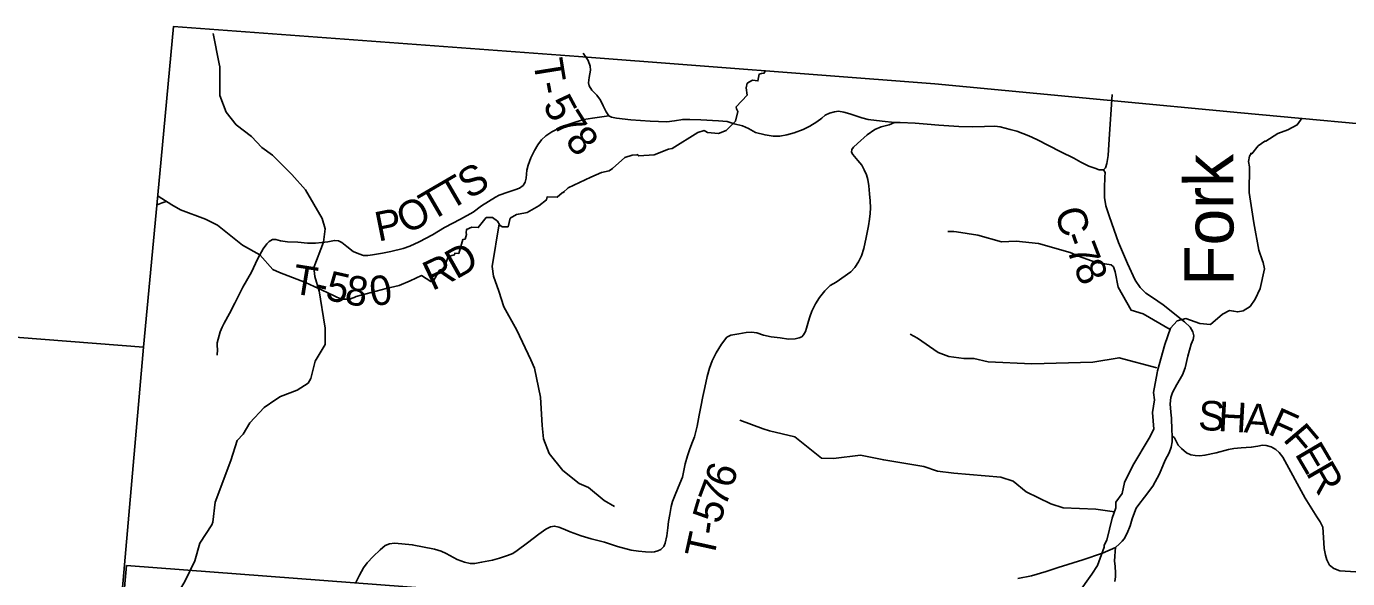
# Model space of a CAD drawing. Extents: x 1878108 to 2183446, y 146837 to 508383.
# Drawn here: x 1945764 to 1959185, y 305217 to 310824 of the extents above; entities that cross this region are included whole.
import ezdxf

# ---------------------------------------------------------------- set-up
doc = ezdxf.new("R2010")
doc.units = 0
for name, color, linetype in [('GM_X_Adjacent_County', 7, 'Continuous'), ('GM_X_County', 7, 'Continuous'), ('GM_X_County_Road', 7, 'Continuous'), ('GM_X_County_Road_Text', 7, 'Continuous'), ('GM_X_Minor_River', 7, 'Continuous'), ('GM_X_Minor_River_Text', 7, 'Continuous'), ('GM_X_Section', 7, 'Continuous'), ('GM_X_Township', 7, 'Continuous'), ('GM_X_Township_Road', 7, 'Continuous'), ('GM_X_Township_Road_Text', 7, 'Continuous')]:
    doc.layers.add(name, color=color, linetype=linetype)

msp = doc.modelspace()

# ---------------------------------------------------------------- linework, layer by layer
at = {"layer": 'GM_X_Adjacent_County'}
for points in [[(1959932, 309778), (1958100, 309945), (1956742, 310075), (1954993, 310242), (1951372, 310518), (1947259, 310824), (1947119, 309329), (1946953, 307566), (1940781, 308049), (1940473, 308073), (1934622, 308532), (1932946, 308617), (1931071, 308772), (1925774, 309211), (1919831, 309702), (1917959, 309848)], [(1923046, 277654), (1923342, 280921), (1923726, 285166), (1924414, 292311), (1924469, 293153), (1924887, 299587), (1925256, 303586), (1925774, 309211), (1931071, 308772), (1932946, 308617), (1934622, 308532), (1940473, 308073), (1940781, 308049), (1946953, 307566), (1946499, 302372), (1946238, 299382), (1946067, 297426), (1944907, 283849), (1944903, 283729), (1945544, 283670), (1949278, 283311), (1954438, 282859), (1961539, 282259)]]:
    msp.add_lwpolyline(points, dxfattribs=at)
at = {"layer": 'GM_X_County'}
msp.add_lwpolyline([(1961539, 282259), (1954438, 282859), (1949278, 283311), (1945544, 283670), (1944903, 283729), (1944907, 283849), (1946067, 297426), (1946238, 299382), (1946499, 302372), (1946953, 307566), (1947119, 309329), (1947259, 310824), (1951372, 310518), (1954993, 310242), (1956742, 310075), (1958100, 309945), (1959932, 309778)], dxfattribs=at)
at = {"layer": 'GM_X_County_Road'}
for points in [[(1956794, 310133), (1956762, 309678), (1956752, 309514), (1956741, 309433), (1956727, 309389), (1956706, 309368), (1956723, 309340), (1956718, 309292), (1956715, 309185), (1956715, 309087), (1956728, 309001), (1956767, 308892), (1956857, 308631), (1956949, 308416), (1957026, 308247), (1957077, 308173), (1957134, 308114), (1957202, 308072), (1957313, 307996), (1957528, 307824), (1957586, 307769), (1957614, 307722), (1957622, 307681), (1957615, 307645), (1957597, 307596), (1957562, 307474), (1957536, 307357), (1957508, 307287), (1957452, 307188), (1957408, 307107), (1957390, 307056), (1957382, 306990), (1957391, 306907), (1957397, 306847), (1957398, 306727), (1957403, 306665), (1957427, 306645), (1957464, 306573), (1957499, 306539), (1957549, 306494), (1957592, 306474), (1957638, 306465), (1957684, 306464), (1957735, 306470), (1957849, 306493), (1957975, 306527), (1958030, 306538), (1958105, 306543), (1958207, 306550), (1958273, 306561), (1958321, 306570), (1958358, 306569), (1958409, 306555), (1958457, 306527), (1958490, 306496), (1958527, 306450), (1958753, 306033), (1958873, 305843), (1958908, 305792), (1958932, 305740), (1958938, 305687), (1958948, 305521), (1958960, 305453), (1958973, 305408), (1959001, 305354), (1959046, 305320), (1959106, 305297), (1959268, 305285)], [(1955837, 305216), (1955974, 305243), (1956122, 305288), (1956244, 305328), (1956496, 305408), (1956697, 305476), (1956829, 305534), (1956868, 305570), (1956894, 305595), (1956915, 305620), (1956947, 305677), (1956976, 305751), (1956997, 305823), (1957022, 305887), (1957038, 305931), (1957066, 305969), (1957122, 306042), (1957207, 306156), (1957273, 306280), (1957331, 306418), (1957371, 306495), (1957393, 306551), (1957402, 306606), (1957403, 306665)]]:
    msp.add_lwpolyline(points, dxfattribs=at)
at = {"layer": 'GM_X_Minor_River'}
for points in [[(1948737, 308134), (1948693, 308284), (1948683, 308375), (1948781, 308632), (1948798, 308767), (1948769, 308874), (1948598, 309163), (1948461, 309321), (1948265, 309518), (1948156, 309595), (1948051, 309705), (1947895, 309826), (1947793, 309954), (1947730, 310121), (1947728, 310413), (1947724, 310443), (1947663, 310751)], [(1947101, 309102), (1947243, 309012), (1947329, 308960), (1947582, 308866), (1947706, 308805), (1947840, 308697), (1947961, 308603), (1948135, 308503), (1948269, 308354), (1948334, 308324), (1948600, 308222), (1948818, 308123), (1948961, 308055), (1949047, 308055), (1949095, 308071), (1949113, 308083), (1949419, 308162), (1949551, 308192), (1949663, 308240), (1949779, 308293), (1949871, 308235), (1949899, 308239), (1949959, 308349), (1949991, 308359), (1950016, 308391), (1950050, 308487), (1950114, 308505), (1950116, 308521), (1950156, 308519), (1950196, 308659), (1950220, 308665), (1950234, 308711), (1950232, 308727), (1950236, 308763), (1950288, 308784), (1950354, 308782), (1950393, 308832), (1950435, 308882), (1950499, 308884), (1950548, 308848), (1950574, 308806), (1950598, 308788), (1950658, 308790), (1950678, 308876), (1950741, 308914), (1950763, 308919), (1950852, 308933), (1950971, 309001), (1951047, 309063), (1951053, 309093), (1951155, 309089), (1951205, 309133), (1951229, 309148), (1951217, 309137), (1951269, 309186), (1951497, 309292), (1951605, 309340), (1951683, 309356), (1951717, 309382), (1951843, 309493), (1951917, 309517), (1951967, 309521), (1951967, 309523), (1951985, 309509), (1952141, 309519), (1952287, 309576), (1952323, 309584), (1952586, 309748), (1952648, 309766), (1952684, 309748), (1952795, 309737), (1952874, 309767), (1952966, 309861), (1952992, 309961), (1952978, 309987), (1952974, 310007), (1953086, 310127), (1953075, 310201), (1953085, 310247), (1953139, 310279), (1953195, 310270), (1953207, 310338), (1953233, 310346), (1953260, 310351), (1953269, 310373)], [(1956446, 305061), (1956586, 305261), (1956643, 305351), (1956713, 305536), (1956713, 305556), (1956741, 305606), (1956792, 305830), (1956832, 305934), (1956830, 305992), (1956894, 306082), (1956919, 306192), (1957003, 306366), (1957168, 306643), (1957218, 306735), (1957202, 306903), (1957223, 307033), (1957215, 307105), (1957250, 307305), (1957254, 307327), (1957328, 307593), (1957387, 307759), (1957453, 307833), (1957541, 307857), (1957683, 307806), (1957791, 307798), (1957913, 307902), (1957985, 307938), (1958027, 307934), (1958069, 307924), (1958123, 307936), (1958195, 307981), (1958247, 308053), (1958297, 308163), (1958342, 308361), (1958326, 308427), (1958322, 308443), (1958282, 308551), (1958231, 308831), (1958184, 309139), (1958189, 309399), (1958177, 309453), (1958187, 309505), (1958205, 309535), (1958211, 309531), (1958199, 309535), (1958211, 309529), (1958275, 309611), (1958343, 309659), (1958353, 309659), (1958477, 309737), (1958577, 309774), (1958674, 309824), (1958707, 309871), (1958718, 309890)], [(1947093, 309012), (1947143, 309031), (1947185, 309047)], [(1950565, 308820), (1950494, 308387), (1950509, 308289), (1950563, 308135), (1950614, 307978), (1950747, 307740), (1950887, 307437), (1950925, 307352), (1950985, 307058), (1951002, 306773), (1951017, 306636), (1951073, 306487), (1951213, 306315), (1951379, 306181), (1951473, 306142), (1951634, 306008), (1951739, 305949)], [(1957383, 307746), (1957107, 307907), (1956987, 307941), (1956854, 308175), (1956825, 308332), (1956808, 308381), (1956782, 308403), (1956630, 308426), (1956450, 308490), (1956366, 308528), (1956045, 308620), (1955818, 308644), (1955671, 308638), (1955430, 308703), (1955213, 308737), (1955186, 308741), (1955125, 308741)], [(1948736, 308160), (1948800, 307760), (1948800, 307593), (1948698, 307425), (1948654, 307249), (1948627, 307202), (1948516, 307130), (1948345, 307067), (1948298, 307036), (1948180, 306953), (1948033, 306798), (1947965, 306684), (1947906, 306620), (1947842, 306417), (1947682, 305992), (1947659, 305788), (1947647, 305761), (1947526, 305578), (1947475, 305396), (1947374, 305186), (1947218, 304925), (1947066, 304787), (1947042, 304678), (1947028, 304297)], [(1957246, 307358), (1956864, 307459), (1956597, 307414), (1955979, 307396), (1955533, 307418), (1955389, 307452), (1955286, 307453), (1955133, 307472), (1955027, 307511), (1954816, 307658), (1954743, 307698)], [(1956818, 305896), (1956626, 305920), (1956297, 305936), (1956172, 305977), (1955919, 306099), (1955788, 306206), (1955662, 306247), (1955184, 306286), (1955019, 306307), (1954880, 306355), (1954473, 306421), (1954237, 306471), (1953964, 306437), (1953841, 306438), (1953569, 306655), (1953314, 306717), (1953247, 306739), (1953010, 306826)]]:
    msp.add_lwpolyline(points, dxfattribs=at)
at = {"layer": 'GM_X_Section'}
msp.add_lwpolyline([(1946780, 305351), (1953640, 304827), (1953129, 299324), (1946292, 299873), (1946481, 302005)], close=True, dxfattribs=at)
at = {"layer": 'GM_X_Township'}
msp.add_lwpolyline([(1961539, 282259), (1954438, 282859), (1949278, 283311), (1945544, 283670), (1944903, 283729), (1944907, 283849), (1946067, 297426), (1946238, 299382), (1946499, 302372), (1946953, 307566), (1947119, 309329), (1947259, 310824), (1951372, 310518), (1954993, 310242), (1956742, 310075), (1958100, 309945), (1959932, 309778)], dxfattribs=at)
at = {"layer": 'GM_X_Township_Road'}
for points in [[(1951421, 310554), (1951470, 310479), (1951491, 310421), (1951494, 310381), (1951482, 310304), (1951474, 310251), (1951481, 310220), (1951508, 310176), (1951559, 310125), (1951596, 310076), (1951624, 310019), (1951652, 309956), (1951681, 309915), (1951707, 309901), (1951757, 309894), (1951905, 309875), (1952102, 309862), (1952270, 309856), (1952346, 309864), (1952431, 309879), (1952505, 309880), (1952616, 309874), (1952796, 309867), (1952882, 309858), (1952954, 309834), (1953037, 309813), (1953098, 309787), (1953169, 309748), (1953268, 309722), (1953351, 309710), (1953418, 309710), (1953488, 309723), (1953563, 309745), (1953655, 309778), (1953722, 309810), (1953794, 309856), (1953844, 309891), (1953879, 309923), (1953921, 309943), (1953972, 309958), (1954015, 309962), (1954068, 309954), (1954130, 309937), (1954249, 309895), (1954314, 309879), (1954458, 309863), (1954581, 309850)], [(1947703, 307487), (1947704, 307544), (1947703, 307579), (1947703, 307611), (1947712, 307647), (1947734, 307723), (1947753, 307769), (1947773, 307811), (1947826, 307908), (1947881, 308013), (1947964, 308175), (1948051, 308329), (1948092, 308417), (1948120, 308475), (1948170, 308564), (1948206, 308616), (1948231, 308639), (1948264, 308660), (1948299, 308661), (1948345, 308648), (1948417, 308636), (1948523, 308632), (1948620, 308624), (1948702, 308624), (1948766, 308629), (1948825, 308636), (1948893, 308651), (1948933, 308646), (1948968, 308630), (1949019, 308590), (1949085, 308540), (1949140, 308513), (1949187, 308499), (1949231, 308499), (1949279, 308505), (1949382, 308523), (1949465, 308540), (1949591, 308569), (1949660, 308593), (1949754, 308636), (1949888, 308709), (1950011, 308782), (1950174, 308866), (1950303, 308938), (1950387, 309001), (1950531, 309089), (1950567, 309110), (1950654, 309142), (1950725, 309163), (1950773, 309181), (1950810, 309208), (1950831, 309243), (1950840, 309284), (1950848, 309363), (1950860, 309416), (1950888, 309489), (1950927, 309564), (1950959, 309620), (1950995, 309671), (1951041, 309712), (1951102, 309754), (1951169, 309788), (1951269, 309828), (1951350, 309855), (1951426, 309880), (1951515, 309894), (1951681, 309915)], [(1949111, 305178), (1949147, 305251), (1949190, 305326), (1949226, 305375), (1949286, 305441), (1949357, 305507), (1949410, 305551), (1949454, 305570), (1949502, 305575), (1949579, 305569), (1949683, 305560), (1949910, 305516), (1949978, 305494), (1950028, 305472), (1950139, 305411), (1950213, 305384), (1950272, 305371), (1950319, 305370), (1950388, 305382), (1950500, 305405), (1950570, 305424), (1950651, 305450), (1950704, 305473), (1950750, 305503), (1950856, 305580), (1950968, 305667), (1951041, 305718), (1951087, 305742), (1951128, 305750), (1951174, 305740), (1951218, 305723), (1951287, 305693), (1951401, 305652), (1951501, 305622), (1951636, 305585), (1951769, 305544), (1951908, 305506), (1951981, 305494), (1952052, 305488), (1952110, 305484), (1952145, 305488), (1952177, 305497), (1952209, 305513), (1952238, 305541), (1952254, 305577), (1952269, 305652), (1952279, 305733), (1952288, 305796), (1952299, 305869), (1952315, 305948), (1952329, 305998), (1952349, 306051), (1952384, 306142), (1952428, 306248), (1952456, 306382), (1952480, 306463), (1952503, 306534), (1952529, 306604), (1952551, 306657), (1952566, 306711), (1952578, 306766), (1952599, 306877), (1952614, 306960), (1952636, 307065), (1952656, 307157), (1952679, 307269), (1952703, 307353), (1952731, 307429), (1952772, 307510), (1952825, 307598), (1952879, 307667), (1952919, 307689), (1953001, 307702), (1953076, 307717), (1953130, 307718), (1953185, 307711), (1953253, 307689), (1953331, 307671), (1953421, 307660), (1953507, 307648), (1953574, 307652), (1953613, 307660), (1953640, 307672), (1953659, 307691), (1953679, 307725), (1953687, 307761), (1953710, 307831), (1953722, 307874), (1953744, 307933), (1953780, 308007), (1953820, 308071), (1953876, 308139), (1953930, 308193), (1953990, 308227), (1954140, 308333), (1954178, 308376), (1954216, 308435), (1954248, 308496), (1954270, 308568), (1954293, 308682), (1954319, 308798), (1954330, 308868), (1954335, 308925), (1954338, 308983), (1954336, 309054), (1954330, 309124), (1954321, 309206), (1954310, 309270), (1954297, 309316), (1954273, 309368), (1954249, 309415), (1954210, 309464), (1954160, 309522), (1954147, 309546), (1954149, 309573), (1954165, 309597), (1954205, 309636), (1954306, 309722), (1954384, 309776), (1954447, 309805), (1954529, 309825), (1954581, 309850), (1954640, 309850), (1954792, 309843), (1954914, 309830), (1955032, 309820), (1955235, 309807), (1955375, 309804), (1955497, 309808), (1955600, 309811), (1955657, 309803), (1955756, 309779), (1955826, 309761), (1955947, 309714), (1956030, 309676), (1956271, 309552), (1956404, 309486), (1956476, 309447), (1956555, 309406), (1956617, 309384), (1956663, 309369), (1956706, 309368)], [(1956821, 305188), (1956829, 305234), (1956828, 305276), (1956823, 305340), (1956818, 305398), (1956819, 305440), (1956825, 305494), (1956829, 305534)]]:
    msp.add_lwpolyline(points, dxfattribs=at)

# ---------------------------------------------------------------- texts
at = {"layer": 'GM_X_County_Road_Text'}
for s, rotation, p in [('C', 285.8143, (1956209, 308946)), ('-', 289.2873, (1956282, 308690)), ('7', 291.1285, (1956327, 308564)), ('8', 293.5311, (1956398, 308379)), ('S', 356.7816, (1957662, 306728)), ('H', 356.7744, (1957864, 306716)), ('A', 355.9057, (1958127, 306702)), ('F', 335.7751, (1958363, 306690)), ('F', 310.2758, (1958520, 306628)), ('E', 300.4548, (1958643, 306484)), ('R', 300.114, (1958756, 306291))]:
    msp.add_text(s, height=300, rotation=rotation, dxfattribs=at).set_placement(p)
at = {"layer": 'GM_X_Minor_River_Text'}
msp.add_text('Fork', height=500, rotation=90.1054, dxfattribs=at).set_placement((1958027, 308192))
at = {"layer": 'GM_X_Township_Road_Text'}
for s, rotation, p in [('T', 279.1368, (1950911, 310475)), ('-', 280.4279, (1950948, 310246)), ('5', 298.3876, (1951004, 310028)), ('7', 302.2304, (1951103, 309847)), ('8', 309.4057, (1951226, 309657)), ('S', 30.2181, (1950259, 309064)), ('T', 30.2531, (1949871, 308838)), ('T', 30.2196, (1950065, 308951)), ('P', 11.3444, (1949338, 308638)), ('O', 27.6386, (1949624, 308709)), ('D', 29.4438, (1950129, 308251)), ('T', 350.8325, (1948452, 308115)), ('R', 25.3841, (1949886, 308135)), ('5', 347.2815, (1948789, 308054)), ('8', 350.2277, (1948986, 308010)), ('0', 9.711, (1949278, 307978)), ('-', 347.3857, (1948669, 308080)), ('6', 72.2917, (1952932, 306121)), ('7', 69.4385, (1952862, 305932)), ('5', 73.4942, (1952811, 305761)), ('-', 82.0218, (1952797, 305650)), ('T', 77.6364, (1952744, 305406))]:
    msp.add_text(s, height=300, rotation=rotation, dxfattribs=at).set_placement(p)

doc.saveas('drawing.dxf')
